Omron CX-Programmer project 新工程 (CX-Programmer 9.50)

# PLC 新PLC1: CP1E NA

## Global symbols (name address type ; comment)
W0.02 BOOL  ; 报警灯
W0.00 BOOL  ; 启动报警
W0.01 BOOL  ; 复位报警

## Program 新程序1 (cyclic task 0)

### Section 段1

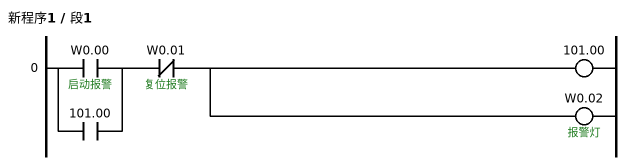
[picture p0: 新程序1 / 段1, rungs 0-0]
; rung 0
LD W0.00  ; 启动报警
OR 101.00
ANDNOT W0.01  ; 复位报警
OUT 101.00
OUT W0.02  ; 报警灯

### Section 段2
; rung 0
END(001)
